(* Logix 5000 project; controller CompactLogix vendor 1 type 14 code 77 rev 13.15; software revision 13.03 *)

TASK MainTask (continuous, watchdog 500 ms) : MainProgram

MODULES
   Controller : vendor 1 type 14 code 77 (CompactLogixL32EController 0, rev 13.15)
      LocalENB : 1769-L32E Ethernet Port (CompactLogixL32Ethernet 1, rev 13.1)
      Local : CompactBus (CompactVirtualAdapter 3, rev 13.1, Input RPI 2 ms)
         DPM : 1769-MODULE (Compact 1, rev 1.1, Output RPI 2 ms)   // 1769-DPM PROFIBUS Master
END_MODULES

TYPE DPM_DEV_COMMAND_REGISTER :   // Device Command Register
STRUCT
   Reserved0 : BOOL;   // Reserved
   Reserved1 : BOOL;   // Reserved
   Reserved2 : BOOL;   // Reserved
   Reserved3 : BOOL;   // Reserved
   Reserved4 : BOOL;   // Reserved
   NRdy : BOOL;   // Application Not Ready
   Init : BOOL;   // Init ( Warm boot )
   Reset : BOOL;   // Reset ( Cold boot )
   HsReq0 : BOOL;   // Slave Diag Request
   HsReq1 : BOOL;   // Global Control Request
   HsReq2 : BOOL;   // Reserved
   HsReq3 : BOOL;   // Reserved
   HsReq4 : BOOL;   // Reserved
   HsReq5 : BOOL;   // Reserved
   HsReq6 : BOOL;   // Reserved
   HsReq7 : BOOL;   // Reserved
   Reserved5 : SINT;   // Reserved
   Reserved6 : SINT;   // Reserved
END_STRUCT
END_TYPE

TYPE DPM_DEV_STATUS_REGISTER :   // Device Status Register
STRUCT
   Reserved0 : BOOL;
   Reserved1 : BOOL;
   Reserved2 : BOOL;
   Reserved3 : BOOL;
   Reserved4 : BOOL;
   Com : BOOL;   // Communication
   Run : BOOL;   // Running
   Rdy : BOOL;   // Ready
   HsAck0 : BOOL;   // Slave Diag Acknowledge
   HsAck1 : BOOL;   // Global Control Acknowledge
   HsAck2 : BOOL;
   HsAck3 : BOOL;
   HsAck4 : BOOL;
   HsAck5 : BOOL;
   HsAck6 : BOOL;
   HsAck7 : BOOL;
   Reserved5 : SINT;
   Reserved6 : SINT;
END_STRUCT
END_TYPE

TYPE DPM_DPV1_ALARM_INDICATION :   // DPV1 Alarm Indication
STRUCT
   AlarmIndication : BOOL;   // Indicates an alarm
   Reserved1 : BOOL;
   Reserved2 : BOOL;
   Reserved3 : BOOL;
   Reserved4 : BOOL;
   Reserved5 : BOOL;
   Reserved6 : BOOL;
   AlarmOverrun : BOOL;   // Overflow of the modules internal alarm buffer
   AlarmCnt : SINT;   // Alarm indication counter
   RemoteAddress : SINT;   // Address of Slave with Alarm
   Slot : SINT;   // Slot Number
   Sequence : SINT;   // Sequence Number
   AlarmType : SINT;   // Alarm Type
   AlarmSpec : SINT;   // Alarm Specification
   Reserved7 : SINT;
END_STRUCT
END_TYPE

TYPE DPM_FW_REVISION :   // Firmware Major/Minor Revision
STRUCT
   FwMinor : SINT;   // Firmware Minor Revison
   FwMajor : SINT;   // Firmware Major Revison
   Reserved : INT;   // Reserved
END_STRUCT
END_TYPE

TYPE DPM_GLOBAL_CONTROL_COMMAND :   // Global Control Command
STRUCT
   SlaveAddress : SINT;   // Slave Address
   ControlCommand : SINT;   // Control Command to be send
   GroupSelect : SINT;   // Group Select
   Reserved1 : SINT;
END_STRUCT
END_TYPE

TYPE DPM_GLOBAL_STATE_FIELD :   // PROFIBUS Master Global State Field
STRUCT
   Ctrl : BOOL;   // Control error
   Aclr : BOOL;   // Auto clear error
   Nexc : BOOL;   // Non exchange error
   Fat : BOOL;   // Fatal error
   Eve : BOOL;   // Event error
   NRdy : BOOL;   // Host not ready notification
   Tout : BOOL;   // Timeout
   Reserved1 : BOOL;   // Reserved
   DPM_State : SINT;   // Master main state
   Err_rem_adr : SINT;   // Faulty remote address
   Err_event : SINT;   // Error Number
   Bus_err_cnt : INT;   // Heavy bus error counter
   Time_out_cnt : INT;   // Number of rejected PROFIBUS Telegr.
   Reserved : SINT[8];   // Reserved
   Sl_cfg : BOOL[128];   // Slave Config
   Sl_state : BOOL[128];   // Slave State
   Sl_diag : BOOL[128];   // Slave Diag
END_STRUCT
END_TYPE

TYPE DPM_INPUT_ARRAY :
STRUCT
   DevStaReg : DPM_DEV_STATUS_REGISTER;
   FwRev : DPM_FW_REVISION;
   GlobStateField : DPM_GLOBAL_STATE_FIELD;
   SlaveDiag : DPM_SLAVE_DIAG_DATA;
   AlarmInd : DPM_DPV1_ALARM_INDICATION;
   InputData : SINT[408];   // PROFIBUS Input data.
END_STRUCT
END_TYPE

TYPE DPM_OUTPUT_ARRAY :
STRUCT
   DevCmdReg : DPM_DEV_COMMAND_REGISTER;
   DiagReqAdr : DPM_SLAVE_DIAG_COMMAND;
   GlobCtrl : DPM_GLOBAL_CONTROL_COMMAND;
   Reserved : SINT[4];
   OutputData : SINT[480];   // PROFIBUS Output data.
END_STRUCT
END_TYPE

TYPE DPM_SLAVE_DIAG_COMMAND :   // Requested address for SlaveDiagnostics
STRUCT
   SlaveAddress : SINT;
   Function : SINT;
   Reserved1 : SINT;
   Reserved2 : SINT;
END_STRUCT
END_TYPE

TYPE DPM_SLAVE_DIAG_DATA :   // Slave standard diagnostic data according to PROFIBUS norm.
STRUCT
   SlaveAddress : SINT;   // Slave address
   DiagFailure : SINT;   // Slave Diag Failure
   Sta1_StationNotExist : BOOL;   // No response
   Sta1_StationNotReady : BOOL;   // Station not ready
   Sta1_CfgFault : BOOL;   // Configuration faulty
   Sta1_ExtDiag : BOOL;   // Extended diagnostic
   Sta1_NotSupp : BOOL;   // Sync,Freeze not supported
   Sta1_InvalidResponse : BOOL;   // Response faulty
   Sta1_PrmFault : BOOL;   // Parameters faulty
   Sta1_MasterLock : BOOL;   // Locked by a master
   Sta2_PrmReq : BOOL;   // Request new parameter
   Sta2_StatDiag : BOOL;   // Static diagnostic
   Sta2_Slave : BOOL;   // Set to 1 by a slave
   Sta2_Watchdog : BOOL;   // Watchdog ON/OFF
   Sta2_FreezeMode : BOOL;   // Freeze mode active
   Sta2_SyncMode : BOOL;   // Sync mode active
   Sta2_Reserved : BOOL;   // Reserved
   Sta2_Deactivated : BOOL;   // Slave deactivated
   Sta3_Reserved0 : BOOL;   // Reserved
   Sta3_Reserved1 : BOOL;   // Reserved
   Sta3_Reserved2 : BOOL;   // Reserved
   Sta3_Reserved3 : BOOL;   // Reserved
   Sta3_Reserved4 : BOOL;   // Reserved
   Sta3_Reserved5 : BOOL;   // Reserved
   Sta3_Reserved6 : BOOL;   // Reserved
   Sta3_ExtDiagOverflow : BOOL;   // Extended diagnostic overflow
   MasterAddress : SINT;   // Corresponding master address
   IdentNumber : INT;   // PROFIBUS Ident number
END_STRUCT
END_TYPE

VAR_GLOBAL   (* controller tags *)
   DoIOGlobCtrl : BOOL;
   DoIOSlaveDiag : BOOL;
   DpmInputArray : DPM_INPUT_ARRAY;
   DpmOutputArray : DPM_OUTPUT_ARRAY;
        .GLOBCTRL.CONTROLCOMMAND   // Control Command to be Sent
END_VAR

PROGRAM MainProgram   (* routine attr 65 MainRoutine *)

ROUTINE IO_Global_Control   (* ladder *)
// Sample routine to execute a PROFIBUS Global Control Request via I/O area
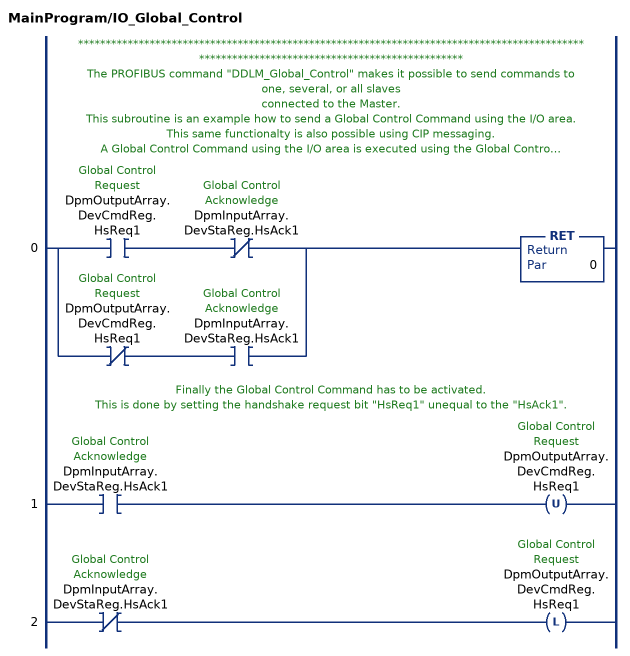
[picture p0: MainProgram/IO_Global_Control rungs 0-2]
   // ********************************************************************************************************************************************
   // The PROFIBUS command "DDLM_Global_Control" makes it possible to send commands to one, several, or all slaves
   //  connected to the Master.
   // This subroutine is an example how to send a Global Control Command using the I/O area.
   // This same functionalty is also possible using CIP messaging.
   // A Global Control Command using the I/O area is executed using the Global Control Command data in the output array
   // to determine the command that has to be sent
   // and the corresponding handshake bits (HsReq1 / HsAck1)
   // in the Device Command Register and Device Status Register in the I/O array are used to activate the command.
   // 1) Check if no Global Control is outstanding. The corresponding handshake bits have to be equal.
   // 2) Fill in the Global Control Command in the output array that has to be sent.
   // 3) Activate the command by flipping the HsReq1bit to unequal to the HsAck1 bit.
   // 4) Wait for the communication module to execute the command by checking the HsAck1 bit equal to HsReq1.
   // ********************************************************************************************************************************************
   // The first rung checks if there is a Global Control Command still in progress. In this case the subroutine returns immediately.
   // A Global Control Command is still in progress if the corresponding handshake bits are not equal.
   // If no Global Control Command is in progress the subroutine continous with rung two.
   0: [XIC(DpmOutputArray.DevCmdReg.HsReq1) XIO(DpmInputArray.DevStaReg.HsAck1) ,XIO(DpmOutputArray.DevCmdReg.HsReq1) XIC(DpmInputArray.DevStaReg.HsAck1) ]RET(0);
   // Finally the Global Control Command has to be activated.
   // This is done by setting the handshake request bit "HsReq1" unequal to the "HsAck1".
   1: XIC(DpmInputArray.DevStaReg.HsAck1)OTU(DpmOutputArray.DevCmdReg.HsReq1);
   2: XIO(DpmInputArray.DevStaReg.HsAck1)OTL(DpmOutputArray.DevCmdReg.HsReq1);
END_ROUTINE

ROUTINE IO_Slave_Diag   (* ladder *)
// Sample routine to execute a PROFIBUS Global Control request via I/O area
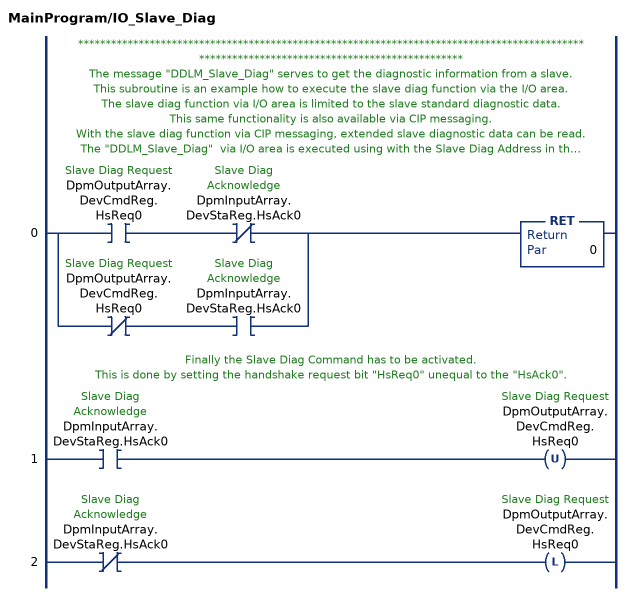
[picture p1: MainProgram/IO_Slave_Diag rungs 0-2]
   // ********************************************************************************************************************************************
   // The message "DDLM_Slave_Diag" serves to get the diagnostic information from a slave.
   // This subroutine is an example how to execute the slave diag function via the I/O area.
   // The slave diag function via I/O area is limited to the slave standard diagnostic data.
   // This same functionality is also available via CIP messaging.
   // With the slave diag function via CIP messaging, extended slave diagnostic data can be read.
   // The "DDLM_Slave_Diag"  via I/O area is executed using with the Slave Diag Address in the output array
   // to determine the slave address and the corresponding handshake bits (HsReq0 / HsAck0)
   // in the Device Command Register and Device Status Register in the I/O array to activate the command.
   // The communication module will return the slave diag result in the input array section for the slave diag data.
   // 1) Check if no "SlaveDiag" is outstanding. The corresponding handshake bits have to be equal.
   // 2) Fill in the SlaveDiagAddress in the output array.
   // 3) Activate the command by flipping the HsReq0 unequal to the HsAck0 bit.
   // 4) Wait for the communication module to execute the command by setting the HsAck0 bit equal to HsReq0.
   // ********************************************************************************************************************************************
   // The first rung checks if there is still a Slave Diag Command in progress. In this case the subroutine returns immediately.
   // A Slave Diag Command is still in progress if the corresponding handshake bits are not equal.
   // If no Slave Diag Command is in progress the subroutine continues with rung two.
   0: [XIC(DpmOutputArray.DevCmdReg.HsReq0) XIO(DpmInputArray.DevStaReg.HsAck0) ,XIO(DpmOutputArray.DevCmdReg.HsReq0) XIC(DpmInputArray.DevStaReg.HsAck0) ]RET(0);
   // Finally the Slave Diag Command has to be activated.
   // This is done by setting the handshake request bit "HsReq0" unequal to the "HsAck0".
   1: XIC(DpmInputArray.DevStaReg.HsAck0)OTU(DpmOutputArray.DevCmdReg.HsReq0);
   2: XIO(DpmInputArray.DevStaReg.HsAck0)OTL(DpmOutputArray.DevCmdReg.HsReq0);
END_ROUTINE

ROUTINE MainRoutine   (* ladder *)
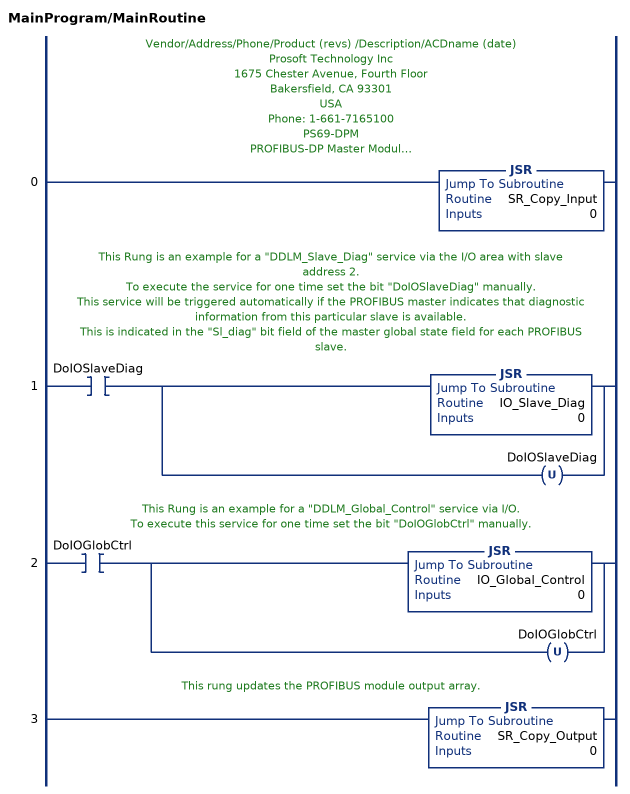
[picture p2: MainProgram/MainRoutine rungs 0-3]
   // Vendor/Address/Phone/Product (revs) /Description/ACDname (date)
   // Prosoft Technology Inc
   // 1675 Chester Avenue, Fourth Floor
   // Bakersfield, CA 93301
   // USA
   // Phone: 1-661-7165100
   // PS69-DPM
   // PROFIBUS-DP Master Module
   // PS69_DPM_L32E.ACD (Rev1.0) (07/28/05)
   // Although this program has been developed with great care and intensively tested,
   // Prosoft Technology Inc cannot guarantee the suitability of this program
   // for any purpose not confirmed by us in writing.
   // We reserve the right to modify our products and their specifications at any time in as far as this contributes to technical progress.
   // The version of the manual supplied with the program applies.
   // Guarantee claims shall be limited to the right to require rectification. Liability for any damages which may have arisen from the use of this program or its documentation shall be limited to cases of intent.
   // This program is a basic example for the setup of the PROFIBUS-DP master communications module "PS69-DPM" in RSLogix5000.
   // This example will show simple PROFIBUS I/O data exchange.  For detailed information about setup and configuration
   // refer to the user manual.
   // The subroutine "SR_Copy_Input" updates the local copy of the PROFIBUS input data from the modules input array.
   0: JSR(SR_Copy_Input,0);
   // This Rung is an example for a "DDLM_Slave_Diag" service via the I/O area with slave address 2.
   // To execute the service for one time set the bit "DoIOSlaveDiag" manually.
   // This service will be triggered automatically if the PROFIBUS master indicates that diagnostic information from this particular slave is available.
   // This is indicated in the "Sl_diag" bit field of the master global state field for each PROFIBUS slave.
   1: XIC(DoIOSlaveDiag)[JSR(IO_Slave_Diag,0) ,OTU(DoIOSlaveDiag) ];
   // This Rung is an example for a "DDLM_Global_Control" service via I/O.
   // To execute this service for one time set the bit "DoIOGlobCtrl" manually.
   2: XIC(DoIOGlobCtrl)[JSR(IO_Global_Control,0) ,OTU(DoIOGlobCtrl) ];
   // This rung updates the PROFIBUS module output array.
   3: JSR(SR_Copy_Output,0);
END_ROUTINE

ROUTINE SR_Copy_Input   (* ladder *)
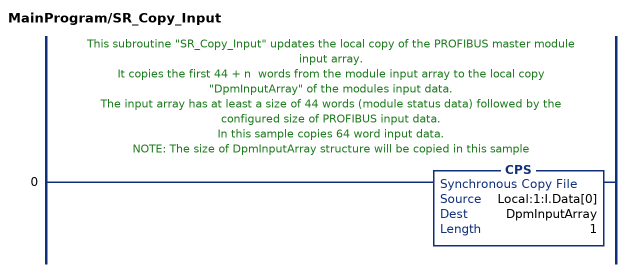
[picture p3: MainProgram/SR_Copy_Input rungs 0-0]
   // This subroutine "SR_Copy_Input" updates the local copy of the PROFIBUS master module input array.
   // It copies the first 44 + n  words from the module input array to the local copy "DpmInputArray" of the modules input data.
   // The input array has at least a size of 44 words (module status data) followed by the configured size of PROFIBUS input data.
   // In this sample copies 64 word input data.
   // NOTE: The size of DpmInputArray structure will be copied in this sample
   0: CPS(Local:1:I.Data[0],DpmInputArray,1);
END_ROUTINE

ROUTINE SR_Copy_Output   (* ladder *)
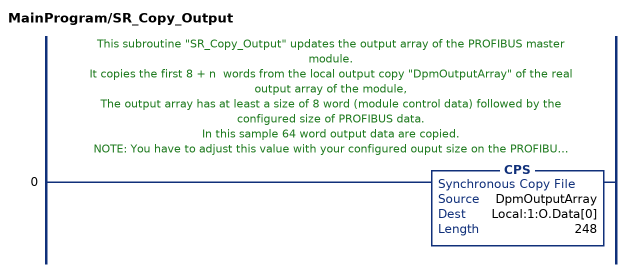
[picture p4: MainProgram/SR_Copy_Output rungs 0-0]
   // This subroutine "SR_Copy_Output" updates the output array of the PROFIBUS master module.
   // It copies the first 8 + n  words from the local output copy "DpmOutputArray" of the real output array of the module,
   // The output array has at least a size of 8 word (module control data) followed by the configured size of PROFIBUS data.
   // In this sample 64 word output data are copied.
   // NOTE: You have to adjust this value with your configured ouput size on the PROFIBUS network and the configured output size in the modules properties dialog Tab:General->Connection Paramter->Output.
   0: CPS(DpmOutputArray,Local:1:O.Data[0],248);
END_ROUTINE
END_PROGRAM
